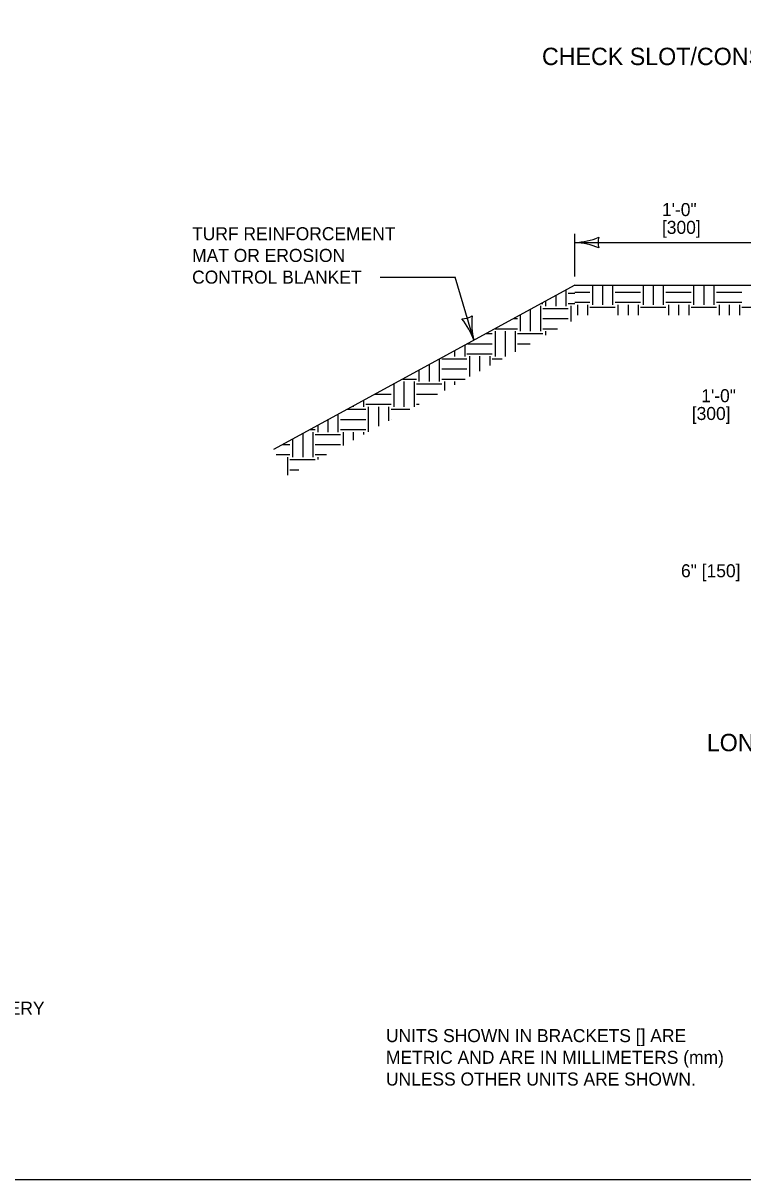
# Model space of a CAD drawing. Extents: x 49977.1 to 50021, y 49987.6 to 50011.4.
# Drawn here: x 50010.27 to 50013.59, y 49987.8 to 49993.13 of the extents above; entities that cross this region are included whole.
import ezdxf

# ---------------------------------------------------------------- set-up
doc = ezdxf.new("R2010")
doc.units = 0
for name, color, linetype in [('Level 1', 7, 'Continuous'), ('Level 2', 7, 'Continuous'), ('Level 3', 7, 'Continuous')]:
    doc.layers.add(name, color=color, linetype=linetype)

msp = doc.modelspace()

# ---------------------------------------------------------------- linework, layer by layer
at = {"layer": 'Level 1'}
for p, q in [((50012.812, 49991.9196), (50011.4243, 49991.1625)), ((50012.7705, 49991.8969), (50012.7705, 49991.8233)), ((50012.8927, 49991.9196), (50012.8927, 49991.8293)), ((50012.9393, 49991.9196), (50012.9393, 49991.8293)), ((50012.9859, 49991.9196), (50012.9859, 49991.8293)), ((50013.1257, 49991.9196), (50013.1257, 49991.8293)), ((50013.1723, 49991.9196), (50013.1723, 49991.8293)), ((50013.2189, 49991.9196), (50013.2189, 49991.8293)), ((50013.3587, 49991.9196), (50013.3587, 49991.8293)), ((50013.4053, 49991.9196), (50013.4053, 49991.8293)), ((50013.4519, 49991.9196), (50013.4519, 49991.8293)), ((50012.6773, 49991.8461), (50012.6773, 49991.8233)), ((50012.7239, 49991.8715), (50012.7239, 49991.8233)), ((50012.7813, 49991.8824), (50012.812, 49991.8824)), ((50012.812, 49991.8876), (50012.8811, 49991.8876)), ((50012.812, 49991.841), (50012.8811, 49991.841)), ((50012.9975, 49991.8876), (50013.114, 49991.8876)), ((50012.9975, 49991.841), (50013.114, 49991.841)), ((50013.2305, 49991.8876), (50013.347, 49991.8876)), ((50013.2305, 49991.841), (50013.347, 49991.841)), ((50013.4635, 49991.8876), (50013.58, 49991.8876)), ((50013.4635, 49991.841), (50013.58, 49991.841)), ((50012.6066, 49991.8075), (50012.6066, 49991.7076)), ((50012.6532, 49991.8241), (50012.6532, 49991.7076)), ((50012.6585, 49991.8358), (50012.6648, 49991.8358)), ((50012.6648, 49991.8125), (50012.7813, 49991.8125)), ((50012.7813, 49991.8358), (50012.812, 49991.8358)), ((50012.793, 49991.8241), (50012.793, 49991.7525)), ((50012.8237, 49991.8293), (50012.8237, 49991.7821)), ((50012.8703, 49991.8293), (50012.8703, 49991.7821)), ((50012.8811, 49991.8185), (50012.9975, 49991.8185)), ((50013.0101, 49991.8293), (50013.0101, 49991.7821)), ((50013.0567, 49991.8293), (50013.0567, 49991.7821)), ((50013.1033, 49991.8293), (50013.1033, 49991.7821)), ((50013.114, 49991.8185), (50013.2305, 49991.8185)), ((50013.2431, 49991.8293), (50013.2431, 49991.7821)), ((50013.2897, 49991.8293), (50013.2897, 49991.7821)), ((50013.3363, 49991.8293), (50013.3363, 49991.7821)), ((50013.347, 49991.8185), (50013.4635, 49991.8185)), ((50013.476, 49991.8293), (50013.476, 49991.7821)), ((50013.5226, 49991.8293), (50013.5226, 49991.7821)), ((50013.5692, 49991.8293), (50013.5692, 49991.7821)), ((50013.58, 49991.8185), (50013.6965, 49991.8185)), ((50012.5304, 49991.7659), (50012.5483, 49991.7659)), ((50012.56, 49991.7821), (50012.56, 49991.7076)), ((50012.6648, 49991.7659), (50012.7813, 49991.7659)), ((50012.4037, 49991.6968), (50012.4318, 49991.6968)), ((50012.4444, 49991.7076), (50012.4444, 49991.5911)), ((50012.4449, 49991.7193), (50012.5483, 49991.7193)), ((50012.491, 49991.7076), (50012.491, 49991.5911)), ((50012.5376, 49991.7076), (50012.5376, 49991.6132)), ((50012.5483, 49991.6968), (50012.6648, 49991.6968)), ((50012.6648, 49991.7193), (50012.732, 49991.7193)), ((50012.6773, 49991.7076), (50012.6773, 49991.6895)), ((50012.3046, 49991.6427), (50012.3046, 49991.5911)), ((50012.3183, 49991.6502), (50012.4318, 49991.6502)), ((50012.5483, 49991.6502), (50012.6054, 49991.6502)), ((50012.1872, 49991.5787), (50012.1872, 49991.4755)), ((50012.1989, 49991.5803), (50012.3153, 49991.5803)), ((50012.2114, 49991.5919), (50012.2114, 49991.5911)), ((50012.258, 49991.6173), (50012.258, 49991.5911)), ((50012.3153, 49991.6036), (50012.4318, 49991.6036)), ((50012.327, 49991.592), (50012.327, 49991.4983)), ((50012.3736, 49991.592), (50012.3736, 49991.5237)), ((50012.4202, 49991.592), (50012.4202, 49991.5492)), ((50012.4318, 49991.5803), (50012.4773, 49991.5803)), ((50012.094, 49991.5278), (50012.094, 49991.4755)), ((50012.1406, 49991.5533), (50012.1406, 49991.4755)), ((50012.1989, 49991.5337), (50012.3153, 49991.5337)), ((50012.0194, 49991.4871), (50012.0824, 49991.4871)), ((50012.025, 49991.4755), (50012.025, 49991.359)), ((50012.0716, 49991.4755), (50012.0716, 49991.359)), ((50012.1989, 49991.4871), (50012.3065, 49991.4871)), ((50012.2114, 49991.4755), (50012.2114, 49991.4352)), ((50012.258, 49991.4755), (50012.258, 49991.4606)), ((50011.8928, 49991.418), (50011.9659, 49991.418)), ((50011.9784, 49991.4647), (50011.9784, 49991.359)), ((50012.0824, 49991.4646), (50012.1989, 49991.4646)), ((50012.0824, 49991.418), (50012.1799, 49991.418)), ((50011.792, 49991.363), (50011.792, 49991.359)), ((50011.8386, 49991.3885), (50011.8386, 49991.359)), ((50011.8494, 49991.3714), (50011.9659, 49991.3714)), ((50012.0824, 49991.3714), (50012.0944, 49991.3714)), ((50011.7212, 49991.3244), (50011.7212, 49991.2433)), ((50011.7646, 49991.3481), (50011.8494, 49991.3481)), ((50011.861, 49991.3598), (50011.861, 49991.2441)), ((50011.9076, 49991.3598), (50011.9076, 49991.2695)), ((50011.9542, 49991.3598), (50011.9542, 49991.2949)), ((50011.9659, 49991.3481), (50012.0517, 49991.3481)), ((50011.5938, 49991.2549), (50011.6164, 49991.2549)), ((50011.628, 49991.2736), (50011.628, 49991.2433)), ((50011.6746, 49991.299), (50011.6746, 49991.2433)), ((50011.7329, 49991.3015), (50011.8494, 49991.3015)), ((50011.7329, 49991.2549), (50011.8494, 49991.2549)), ((50011.9659, 49991.3015), (50011.9663, 49991.3015)), ((50011.5124, 49991.2105), (50011.5124, 49991.1268)), ((50011.559, 49991.2359), (50011.559, 49991.1268)), ((50011.6056, 49991.2433), (50011.6056, 49991.1268)), ((50011.6164, 49991.2325), (50011.7329, 49991.2325)), ((50011.7454, 49991.2433), (50011.7454, 49991.181)), ((50011.792, 49991.2433), (50011.792, 49991.2064)), ((50011.8386, 49991.2433), (50011.8386, 49991.2318)), ((50011.4672, 49991.1859), (50011.4999, 49991.1859)), ((50011.6164, 49991.1859), (50011.7329, 49991.1859)), ((50011.4369, 49991.1393), (50011.4999, 49991.1393)), ((50011.4882, 49991.1276), (50011.4882, 49991.0453)), ((50011.4999, 49991.116), (50011.6164, 49991.116)), ((50011.6164, 49991.1393), (50011.6689, 49991.1393)), ((50011.628, 49991.1276), (50011.628, 49991.117)), ((50011.4999, 49991.0694), (50011.5408, 49991.0694))]:
    msp.add_line(p, q, dxfattribs=at)
msp.add_lwpolyline([(49999.3835, 49998.9992), (50016.7501, 49998.9992), (50016.7501, 49987.7988), (49999.3835, 49987.7988)], close=True, dxfattribs=at)
msp.add_lwpolyline([(50012.812, 49991.9196), (50013.912, 49991.9196), (50013.912, 49990.8196), (50014.462, 49990.8196)], dxfattribs=at)
at = {"layer": 'Level 3'}
for p, q in [((50012.812, 49991.9596), (50012.812, 49992.1559)), ((50012.812, 49992.1159), (50013.912, 49992.1159)), ((50011.9151, 49991.9567), (50012.2611, 49991.9567)), ((50012.3468, 49991.6657), (50012.2611, 49991.9567))]:
    msp.add_line(p, q, dxfattribs=at)
for centre, radius, start, end in [((50012.7953, 49992.4534), 0.3379, 272.8273, 292.0772), ((50012.7987, 49991.7937), 0.3224, 67.456, 87.6395), ((50012.998, 49992.1159), 0.0794, 162.1388, 197.8612), ((50012.2942, 49991.8441), 0.0794, 268.5507, 304.273), ((50012.0277, 49991.5544), 0.3379, 19.2392, 38.489), ((50012.6596, 49991.744), 0.3224, 173.8679, 194.0514)]:
    msp.add_arc(centre, radius, start, end, dxfattribs=at)

# ---------------------------------------------------------------- texts
at = {"layer": 'Level 2'}
for s, height, p in [('CHECK SLOT/CONSECUTIVE ROLL JOINT TRENCH', 0.08, (50012.6604, 49992.9333)), ('1\'-0" ', 0.06, (50013.2128, 49992.2379)), ('[300]', 0.06, (50013.2128, 49992.1559)), ('TURF REINFORCEMENT ', 0.06, (50011.0498, 49992.1267)), ('MAT OR EROSION', 0.06, (50011.0498, 49992.0267)), ('CONTROL BLANKET', 0.06, (50011.0498, 49991.9267)), ('1\'-0" ', 0.06, (50013.3937, 49991.3806)), ('[300]', 0.06, (50013.3502, 49991.2986)), ('6" [150]', 0.06, (50013.3005, 49990.5742)), ('LONGITUDINAL TRENCH', 0.08, (50013.4192, 49989.7731)), ('CHECK SLOT/CONSECUTIVE ROLL JOINT TRENCH: PROVIDE A CHECK SLOT A MINIMUM OF EVERY', 0.06, (50006.5098, 49988.5595)), ('UNITS SHOWN IN BRACKETS [] ARE ', 0.06, (50011.9422, 49988.4332)), ('METRIC AND ARE IN MILLIMETERS (mm) ', 0.06, (50011.9422, 49988.3332)), ('UNLESS OTHER UNITS ARE SHOWN.', 0.06, (50011.9422, 49988.2332))]:
    msp.add_text(s, height=height, dxfattribs=at).set_placement(p)

doc.saveas('drawing.dxf')
